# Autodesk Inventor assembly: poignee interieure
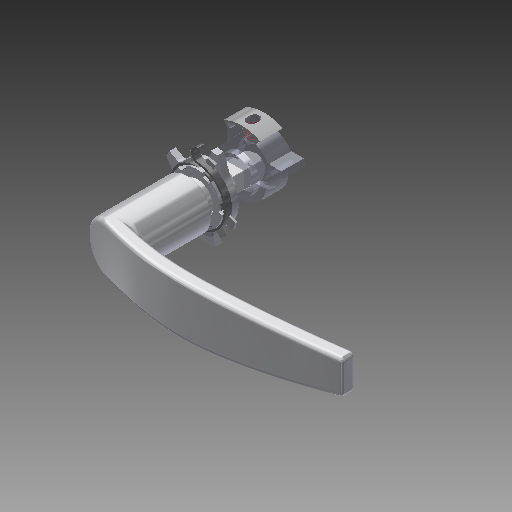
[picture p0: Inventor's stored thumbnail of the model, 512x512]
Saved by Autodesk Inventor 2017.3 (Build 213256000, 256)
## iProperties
Created: 2011-01
Part Number: poignee interieure
Material: Générique
Document SubType Name: Assembly
Designer: ficho
Author: ficho
Sending System: SolidWorks 2009
Last Author: christophe
Last Saved: 2011-02-10
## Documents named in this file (9)
- G:\travail\année 2019-2020\réforme\toussaint\Serrure biométrique SET\Documentations_pedagogique\Modelisation_Solidworks\poignee interieure.iam
- G:\travail\année 2019-2020\réforme\toussaint\Serrure biométrique SET\Documentations_pedagogique\Modelisation_Solidworks\pièce a3.ipt
- G:\travail\année 2019-2020\réforme\toussaint\Serrure biométrique SET\Documentations_pedagogique\Modelisation_Solidworks\bequille.ipt
- G:\travail\année 2019-2020\réforme\toussaint\Serrure biométrique SET\Documentations_pedagogique\Modelisation_Solidworks\pièce a5.ipt
- G:\travail\année 2019-2020\réforme\toussaint\Serrure biométrique SET\Documentations_pedagogique\Modelisation_Solidworks\pièce a16.ipt
- G:\travail\année 2019-2020\réforme\toussaint\Serrure biométrique SET\Documentations_pedagogique\Modelisation_Solidworks\pièce a4.ipt
- G:\travail\année 2019-2020\réforme\toussaint\Serrure biométrique SET\Documentations_pedagogique\Modelisation_Solidworks\pièce a7bis.ipt
- G:\travail\année 2019-2020\réforme\toussaint\Serrure biométrique SET\Documentations_pedagogique\Modelisation_Solidworks\carre.ipt
- G:\travail\année 2019-2020\réforme\toussaint\Serrure biométrique SET\Documentations_pedagogique\Modelisation_Solidworks\Assemblage4.iam
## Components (9 placed, 8 different names)
1. pièce a3:1
2. bequille:1
3. pièce a5:1
4. pièce a16:1
5. pièce a4:1
6. pièce a7bis:1
7. pièce a3:2
8. carre:1
9. Assemblage4:1 [sub-assembly]
